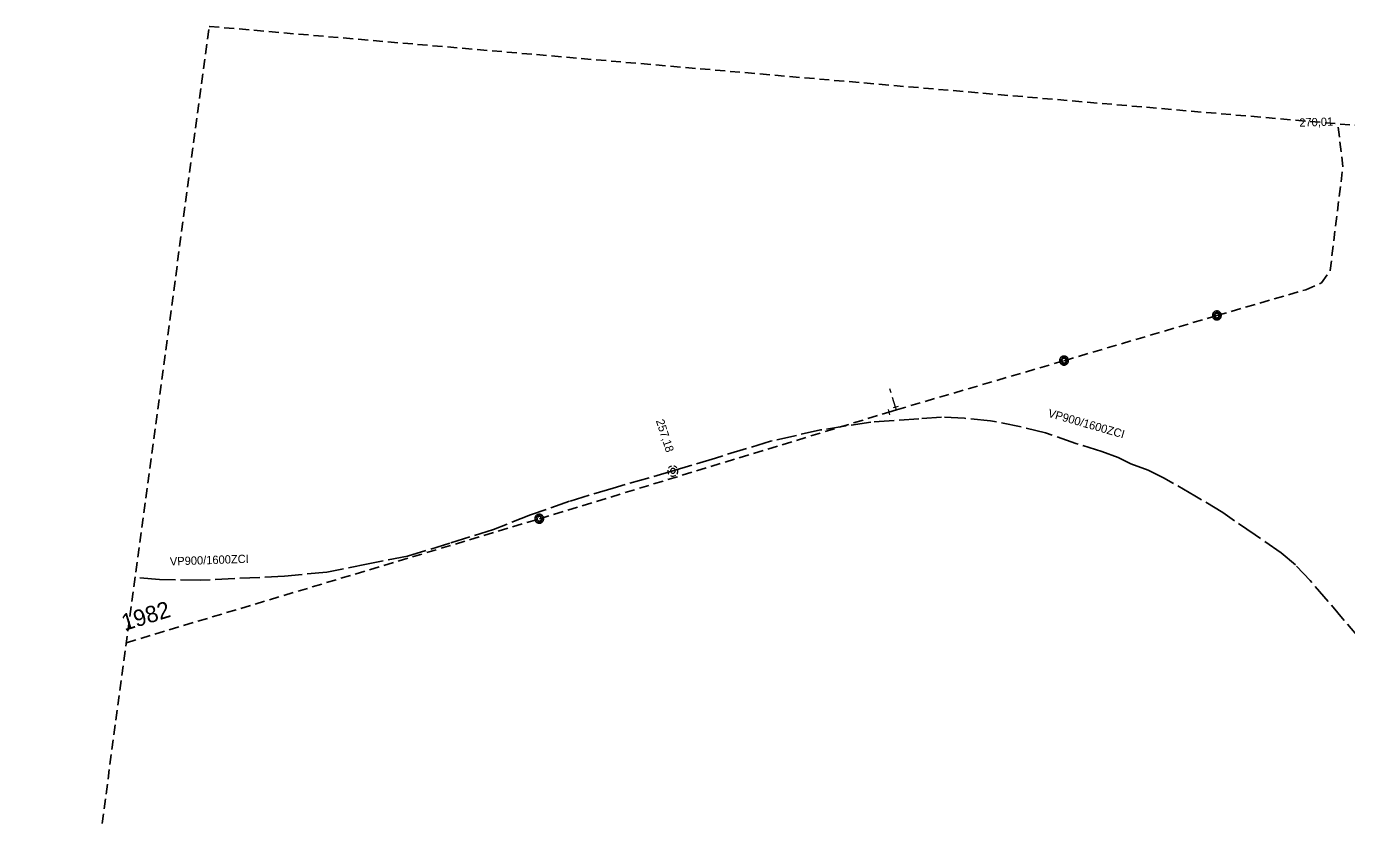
# Model space of a CAD drawing. Extents: x -743212 to -743020, y -1051380 to -1051228.
# Drawn here: x -743211.8 to -743084.5, y -1051304 to -1051227.7 of the extents above; entities that cross this region are included whole.
import ezdxf

# ---------------------------------------------------------------- set-up
doc = ezdxf.new("R2010")
doc.units = 0
doc.header["$LTSCALE"] = 0.32
doc.linetypes.add('LONG_DASHED', pattern=[7.5, 6, -1.5])
doc.linetypes.add('MEDIUM_DASHED', pattern=[4.5, 3, -1.5])
for name, color, linetype, lineweight in [('1', 7, 'MEDIUM_DASHED', 25), ('18', 7, 'Continuous', 13), ('20', 7, 'Continuous', 13), ('8', 7, 'Continuous', 13)]:
    doc.layers.add(name, color=color, linetype=linetype, lineweight=lineweight)

msp = doc.modelspace()

# ---------------------------------------------------------------- linework, layer by layer
at = {"layer": '1'}
msp.add_lwpolyline([(-743035.828, -1051380.323), (-743211.786, -1051358.847), (-743211.788, -1051358.847), (-743211.79, -1051358.846), (-743211.791, -1051358.845), (-743211.793, -1051358.844), (-743211.794, -1051358.842), (-743211.794, -1051358.84), (-743211.795, -1051358.838), (-743211.795, -1051358.836), (-743194.164, -1051227.732), (-743194.163, -1051227.73), (-743194.162, -1051227.729), (-743194.161, -1051227.727), (-743194.16, -1051227.726), (-743194.158, -1051227.725), (-743194.157, -1051227.724), (-743194.155, -1051227.724), (-743194.153, -1051227.724), (-743020.025, -1051242.759)], dxfattribs=at)
at = {"layer": '18'}
for points in [[(-743149.947, -1051270.519), (-743149.953, -1051270.596), (-743149.948, -1051270.673), (-743149.931, -1051270.748), (-743149.902, -1051270.819), (-743149.862, -1051270.885), (-743149.846, -1051270.907)], [(-743149.602, -1051270.127), (-743149.673, -1051270.155), (-743149.74, -1051270.194), (-743149.8, -1051270.242), (-743149.851, -1051270.299), (-743149.875, -1051270.333)], [(-743149.061, -1051270.31), (-743149.111, -1051270.252), (-743149.169, -1051270.202), (-743149.234, -1051270.161), (-743149.305, -1051270.132), (-743149.354, -1051270.118)], [(-743149.066, -1051270.896), (-743149.025, -1051270.831), (-743148.994, -1051270.761), (-743148.975, -1051270.686), (-743148.967, -1051270.61), (-743148.972, -1051270.533), (-743148.978, -1051270.498)], [(-743149.689, -1051271.036), (-743149.619, -1051271.067), (-743149.544, -1051271.086), (-743149.468, -1051271.093), (-743149.391, -1051271.088), (-743149.316, -1051271.071), (-743149.244, -1051271.043), (-743149.184, -1051271.008)]]:
    msp.add_lwpolyline(points, dxfattribs=at)
msp.add_lwpolyline([(-743149.218, -1051270.579), (-743149.224, -1051270.527), (-743149.242, -1051270.477), (-743149.27, -1051270.433), (-743149.308, -1051270.396), (-743149.353, -1051270.369), (-743149.403, -1051270.353), (-743149.455, -1051270.348), (-743149.507, -1051270.355), (-743149.556, -1051270.374), (-743149.6, -1051270.404), (-743149.635, -1051270.443), (-743149.661, -1051270.488), (-743149.676, -1051270.539), (-743149.679, -1051270.591), (-743149.671, -1051270.643), (-743149.65, -1051270.691), (-743149.62, -1051270.734), (-743149.58, -1051270.769), (-743149.534, -1051270.793), (-743149.483, -1051270.807), (-743149.431, -1051270.809), (-743149.379, -1051270.799), (-743149.331, -1051270.777), (-743149.289, -1051270.745), (-743149.256, -1051270.705), (-743149.232, -1051270.658), (-743149.22, -1051270.607)], close=True, dxfattribs=at)
at = {"layer": '20', "linetype": 'LONG_DASHED', "lineweight": 25}
for points in [[(-743083.155, -1051286.838), (-743088, -1051281.159), (-743089.43, -1051279.656), (-743090.807, -1051278.489), (-743093.317, -1051276.75), (-743096.42, -1051274.615), (-743099.107, -1051272.987), (-743102.142, -1051271.267), (-743103.635, -1051270.504), (-743105.296, -1051269.918), (-743106.522, -1051269.301), (-743108.083, -1051268.708), (-743110.6, -1051267.95), (-743113.526, -1051266.926), (-743115.881, -1051266.345), (-743118.818, -1051265.754), (-743121.34, -1051265.52), (-743123.539, -1051265.392), (-743125.734, -1051265.57), (-743130.362, -1051265.892), (-743135.206, -1051266.638), (-743140.048, -1051267.723), (-743145.346, -1051269.347), (-743149.449, -1051270.59)], [(-743083.155, -1051286.838), (-743088, -1051281.159), (-743089.43, -1051279.656), (-743090.807, -1051278.489), (-743093.317, -1051276.75), (-743096.42, -1051274.615), (-743099.107, -1051272.987), (-743102.142, -1051271.267), (-743103.635, -1051270.504), (-743105.296, -1051269.918), (-743106.522, -1051269.301), (-743108.083, -1051268.708), (-743110.6, -1051267.95), (-743113.526, -1051266.926), (-743115.881, -1051266.345), (-743118.818, -1051265.754), (-743121.34, -1051265.52), (-743123.539, -1051265.392), (-743125.734, -1051265.57), (-743130.362, -1051265.892), (-743135.206, -1051266.638), (-743140.048, -1051267.723), (-743145.346, -1051269.347), (-743149.449, -1051270.59)], [(-743149.449, -1051270.59), (-743155.226, -1051272.244), (-743159.408, -1051273.521), (-743163.199, -1051274.842), (-743166.743, -1051276.226), (-743170.969, -1051277.57), (-743175.031, -1051278.808), (-743178.853, -1051279.546), (-743182.809, -1051280.35), (-743186.892, -1051280.737), (-743195.01, -1051281.132), (-743198.952, -1051281.065), (-743201.31, -1051280.875)], [(-743149.449, -1051270.59), (-743155.226, -1051272.244), (-743159.408, -1051273.521), (-743163.199, -1051274.842), (-743166.743, -1051276.226), (-743170.969, -1051277.57), (-743175.031, -1051278.808), (-743178.853, -1051279.546), (-743182.809, -1051280.35), (-743186.892, -1051280.737), (-743195.01, -1051281.132), (-743198.952, -1051281.065), (-743201.31, -1051280.875)]]:
    msp.add_lwpolyline(points, dxfattribs=at)
at = {"layer": '8', "linetype": 'MEDIUM_DASHED', "lineweight": 25}
for p, q in [((-743111.73, -1051259.96), (-743096.989, -1051255.61)), ((-743162.329, -1051275.21), (-743128.627, -1051264.923)), ((-743202.155, -1051287.155), (-743162.329, -1051275.21))]:
    msp.add_line(p, q, dxfattribs=at)
at = {"layer": '8'}
for p, q in [((-743127.735, -1051264.365), (-743128.228, -1051264.521)), ((-743128.702, -1051264.673), (-743128.551, -1051265.168))]:
    msp.add_line(p, q, dxfattribs=at)
at = {"layer": '8', "linetype": 'MEDIUM_DASHED', "lineweight": 25}
for points in [[(-743096.989, -1051255.61), (-743088.43, -1051253.122), (-743086.901, -1051252.467), (-743086.074, -1051251.274), (-743084.849, -1051241.25), (-743085.334, -1051237.12)], [(-743128.627, -1051264.923), (-743127.903, -1051264.702), (-743111.73, -1051259.96)]]:
    msp.add_lwpolyline(points, dxfattribs=at)
at = {"layer": '8'}
for points in [[(-743096.559, -1051255.599), (-743096.562, -1051255.554), (-743096.569, -1051255.509), (-743096.581, -1051255.464), (-743096.597, -1051255.422), (-743096.618, -1051255.381), (-743096.643, -1051255.342), (-743096.672, -1051255.307), (-743096.704, -1051255.274), (-743096.74, -1051255.246), (-743096.777, -1051255.221), (-743096.819, -1051255.2), (-743096.862, -1051255.183), (-743096.906, -1051255.171), (-743096.951, -1051255.164), (-743096.997, -1051255.162), (-743097.043, -1051255.164), (-743097.088, -1051255.171), (-743097.132, -1051255.183), (-743097.175, -1051255.2), (-743097.216, -1051255.221), (-743097.254, -1051255.246), (-743097.29, -1051255.274), (-743097.322, -1051255.307), (-743097.351, -1051255.342), (-743097.376, -1051255.381), (-743097.397, -1051255.422), (-743097.413, -1051255.464), (-743097.425, -1051255.509), (-743097.432, -1051255.554), (-743097.434, -1051255.6), (-743097.432, -1051255.645), (-743097.425, -1051255.69), (-743097.413, -1051255.735), (-743097.397, -1051255.777), (-743097.376, -1051255.818), (-743097.351, -1051255.857), (-743097.322, -1051255.892), (-743097.29, -1051255.925), (-743097.254, -1051255.953), (-743097.216, -1051255.978), (-743097.175, -1051255.999), (-743097.132, -1051256.016), (-743097.088, -1051256.027), (-743097.043, -1051256.035), (-743096.997, -1051256.037), (-743096.951, -1051256.035), (-743096.906, -1051256.027), (-743096.862, -1051256.016), (-743096.819, -1051255.999), (-743096.777, -1051255.978), (-743096.74, -1051255.953), (-743096.704, -1051255.925), (-743096.672, -1051255.892), (-743096.643, -1051255.857), (-743096.618, -1051255.818), (-743096.597, -1051255.777), (-743096.581, -1051255.735), (-743096.569, -1051255.69), (-743096.562, -1051255.645), (-743096.559, -1051255.6)], [(-743111.299, -1051259.949), (-743111.302, -1051259.904), (-743111.309, -1051259.859), (-743111.321, -1051259.814), (-743111.337, -1051259.772), (-743111.358, -1051259.731), (-743111.383, -1051259.692), (-743111.412, -1051259.657), (-743111.444, -1051259.624), (-743111.48, -1051259.596), (-743111.517, -1051259.571), (-743111.559, -1051259.55), (-743111.602, -1051259.533), (-743111.646, -1051259.521), (-743111.691, -1051259.514), (-743111.737, -1051259.512), (-743111.782, -1051259.514), (-743111.828, -1051259.521), (-743111.872, -1051259.533), (-743111.915, -1051259.55), (-743111.956, -1051259.571), (-743111.994, -1051259.596), (-743112.03, -1051259.624), (-743112.062, -1051259.657), (-743112.091, -1051259.692), (-743112.116, -1051259.731), (-743112.137, -1051259.772), (-743112.152, -1051259.814), (-743112.165, -1051259.859), (-743112.172, -1051259.904), (-743112.174, -1051259.95), (-743112.172, -1051259.995), (-743112.165, -1051260.04), (-743112.152, -1051260.085), (-743112.137, -1051260.127), (-743112.116, -1051260.168), (-743112.091, -1051260.207), (-743112.062, -1051260.242), (-743112.03, -1051260.275), (-743111.994, -1051260.303), (-743111.956, -1051260.328), (-743111.915, -1051260.349), (-743111.872, -1051260.366), (-743111.828, -1051260.377), (-743111.782, -1051260.385), (-743111.737, -1051260.387), (-743111.691, -1051260.385), (-743111.646, -1051260.377), (-743111.602, -1051260.366), (-743111.559, -1051260.349), (-743111.517, -1051260.328), (-743111.48, -1051260.303), (-743111.444, -1051260.275), (-743111.412, -1051260.242), (-743111.383, -1051260.207), (-743111.358, -1051260.168), (-743111.337, -1051260.127), (-743111.321, -1051260.085), (-743111.309, -1051260.04), (-743111.302, -1051259.995), (-743111.299, -1051259.95)], [(-743161.899, -1051275.198), (-743161.902, -1051275.153), (-743161.909, -1051275.108), (-743161.921, -1051275.063), (-743161.936, -1051275.021), (-743161.958, -1051274.98), (-743161.983, -1051274.941), (-743162.012, -1051274.906), (-743162.044, -1051274.873), (-743162.08, -1051274.845), (-743162.117, -1051274.82), (-743162.159, -1051274.799), (-743162.201, -1051274.782), (-743162.245, -1051274.77), (-743162.291, -1051274.763), (-743162.337, -1051274.761), (-743162.382, -1051274.763), (-743162.428, -1051274.77), (-743162.472, -1051274.782), (-743162.515, -1051274.799), (-743162.556, -1051274.82), (-743162.593, -1051274.845), (-743162.63, -1051274.873), (-743162.662, -1051274.906), (-743162.691, -1051274.941), (-743162.716, -1051274.98), (-743162.737, -1051275.021), (-743162.752, -1051275.063), (-743162.765, -1051275.108), (-743162.772, -1051275.153), (-743162.774, -1051275.199), (-743162.772, -1051275.244), (-743162.765, -1051275.289), (-743162.752, -1051275.334), (-743162.737, -1051275.376), (-743162.716, -1051275.417), (-743162.691, -1051275.456), (-743162.662, -1051275.491), (-743162.63, -1051275.524), (-743162.593, -1051275.552), (-743162.556, -1051275.577), (-743162.515, -1051275.598), (-743162.472, -1051275.615), (-743162.428, -1051275.626), (-743162.382, -1051275.634), (-743162.337, -1051275.636), (-743162.291, -1051275.634), (-743162.245, -1051275.626), (-743162.201, -1051275.615), (-743162.159, -1051275.598), (-743162.117, -1051275.577), (-743162.08, -1051275.552), (-743162.044, -1051275.524), (-743162.012, -1051275.491), (-743161.983, -1051275.456), (-743161.958, -1051275.417), (-743161.936, -1051275.376), (-743161.921, -1051275.334), (-743161.909, -1051275.289), (-743161.902, -1051275.244), (-743161.899, -1051275.199)]]:
    msp.add_lwpolyline(points, dxfattribs=at)
for points in [[(-743096.673, -1051255.607), (-743096.679, -1051255.546), (-743096.697, -1051255.486), (-743096.726, -1051255.431), (-743096.765, -1051255.383), (-743096.812, -1051255.343), (-743096.866, -1051255.313), (-743096.925, -1051255.293), (-743096.987, -1051255.286), (-743097.049, -1051255.29), (-743097.108, -1051255.306), (-743097.164, -1051255.334), (-743097.214, -1051255.371), (-743097.255, -1051255.418), (-743097.287, -1051255.471), (-743097.307, -1051255.53), (-743097.317, -1051255.591), (-743097.314, -1051255.653), (-743097.299, -1051255.713), (-743097.273, -1051255.77), (-743097.237, -1051255.82), (-743097.191, -1051255.863), (-743097.139, -1051255.895), (-743097.081, -1051255.918), (-743097.02, -1051255.928), (-743096.958, -1051255.927), (-743096.897, -1051255.914), (-743096.84, -1051255.889), (-743096.789, -1051255.854), (-743096.745, -1051255.81), (-743096.711, -1051255.758), (-743096.687, -1051255.701), (-743096.675, -1051255.64)], [(-743096.787, -1051255.607), (-743096.793, -1051255.558), (-743096.809, -1051255.511), (-743096.838, -1051255.47), (-743096.876, -1051255.437), (-743096.92, -1051255.413), (-743096.968, -1051255.401), (-743097.018, -1051255.4), (-743097.066, -1051255.412), (-743097.111, -1051255.434), (-743097.149, -1051255.467), (-743097.178, -1051255.507), (-743097.197, -1051255.554), (-743097.204, -1051255.603), (-743097.199, -1051255.653), (-743097.182, -1051255.7), (-743097.155, -1051255.742), (-743097.118, -1051255.776), (-743097.075, -1051255.8), (-743097.027, -1051255.814), (-743096.977, -1051255.815), (-743096.928, -1051255.805), (-743096.883, -1051255.783), (-743096.844, -1051255.751), (-743096.814, -1051255.712), (-743096.795, -1051255.666), (-743096.787, -1051255.616)], [(-743111.413, -1051259.957), (-743111.419, -1051259.896), (-743111.437, -1051259.836), (-743111.466, -1051259.781), (-743111.505, -1051259.733), (-743111.552, -1051259.693), (-743111.606, -1051259.663), (-743111.665, -1051259.643), (-743111.727, -1051259.636), (-743111.789, -1051259.64), (-743111.848, -1051259.656), (-743111.904, -1051259.684), (-743111.954, -1051259.721), (-743111.995, -1051259.768), (-743112.027, -1051259.821), (-743112.047, -1051259.88), (-743112.057, -1051259.941), (-743112.054, -1051260.003), (-743112.039, -1051260.063), (-743112.013, -1051260.12), (-743111.977, -1051260.17), (-743111.931, -1051260.213), (-743111.879, -1051260.245), (-743111.821, -1051260.268), (-743111.76, -1051260.278), (-743111.698, -1051260.277), (-743111.637, -1051260.264), (-743111.58, -1051260.239), (-743111.529, -1051260.204), (-743111.485, -1051260.16), (-743111.451, -1051260.108), (-743111.427, -1051260.051), (-743111.415, -1051259.99)], [(-743111.527, -1051259.957), (-743111.532, -1051259.908), (-743111.549, -1051259.861), (-743111.578, -1051259.82), (-743111.616, -1051259.787), (-743111.66, -1051259.763), (-743111.708, -1051259.751), (-743111.758, -1051259.75), (-743111.806, -1051259.762), (-743111.851, -1051259.784), (-743111.889, -1051259.817), (-743111.918, -1051259.857), (-743111.937, -1051259.904), (-743111.944, -1051259.953), (-743111.939, -1051260.003), (-743111.922, -1051260.05), (-743111.895, -1051260.092), (-743111.858, -1051260.126), (-743111.815, -1051260.15), (-743111.767, -1051260.164), (-743111.717, -1051260.165), (-743111.668, -1051260.155), (-743111.623, -1051260.133), (-743111.584, -1051260.101), (-743111.554, -1051260.062), (-743111.535, -1051260.016), (-743111.527, -1051259.966)], [(-743162.012, -1051275.206), (-743162.019, -1051275.145), (-743162.037, -1051275.085), (-743162.066, -1051275.03), (-743162.105, -1051274.982), (-743162.152, -1051274.942), (-743162.206, -1051274.912), (-743162.265, -1051274.892), (-743162.326, -1051274.885), (-743162.389, -1051274.889), (-743162.448, -1051274.905), (-743162.504, -1051274.933), (-743162.554, -1051274.97), (-743162.595, -1051275.017), (-743162.627, -1051275.07), (-743162.647, -1051275.129), (-743162.657, -1051275.19), (-743162.654, -1051275.252), (-743162.639, -1051275.312), (-743162.613, -1051275.369), (-743162.576, -1051275.419), (-743162.531, -1051275.462), (-743162.478, -1051275.494), (-743162.421, -1051275.517), (-743162.36, -1051275.527), (-743162.298, -1051275.526), (-743162.237, -1051275.513), (-743162.179, -1051275.488), (-743162.129, -1051275.453), (-743162.085, -1051275.409), (-743162.051, -1051275.357), (-743162.027, -1051275.3), (-743162.015, -1051275.239)], [(-743162.127, -1051275.206), (-743162.132, -1051275.157), (-743162.149, -1051275.11), (-743162.178, -1051275.069), (-743162.216, -1051275.036), (-743162.26, -1051275.012), (-743162.308, -1051275), (-743162.358, -1051274.999), (-743162.406, -1051275.011), (-743162.451, -1051275.033), (-743162.489, -1051275.066), (-743162.517, -1051275.106), (-743162.537, -1051275.153), (-743162.544, -1051275.202), (-743162.539, -1051275.252), (-743162.522, -1051275.299), (-743162.495, -1051275.341), (-743162.458, -1051275.375), (-743162.414, -1051275.399), (-743162.367, -1051275.413), (-743162.316, -1051275.414), (-743162.267, -1051275.404), (-743162.223, -1051275.382), (-743162.184, -1051275.35), (-743162.154, -1051275.311), (-743162.135, -1051275.265), (-743162.127, -1051275.215)]]:
    msp.add_lwpolyline(points, close=True, dxfattribs=at)
at = {"layer": '8', "linetype": 'MEDIUM_DASHED'}
msp.add_lwpolyline([(-743127.903, -1051264.702), (-743127.984, -1051264.443), (-743128.526, -1051262.665)], dxfattribs=at)

# ---------------------------------------------------------------- texts
at = {"layer": '1'}
for s, height, rotation, p in [('270,01', 0.8, 2, (-743089.042, -1051237.405)), ('257,18', 0.8, 288, (-743151.101, -1051265.758)), ('VP900/1600ZCI ', 0.8, 344, (-743113.344, -1051265.364)), ('VP900/1600ZCI ', 0.8, 2, (-743197.948, -1051279.717)), ('1982', 1.6, 17, (-743202.33, -1051286.025))]:
    msp.add_text(s, height=height, rotation=rotation, dxfattribs=at).set_placement(p)

doc.saveas('drawing.dxf')
